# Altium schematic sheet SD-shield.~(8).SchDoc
size A; SheetNumber: 1; SheetTotal: 1
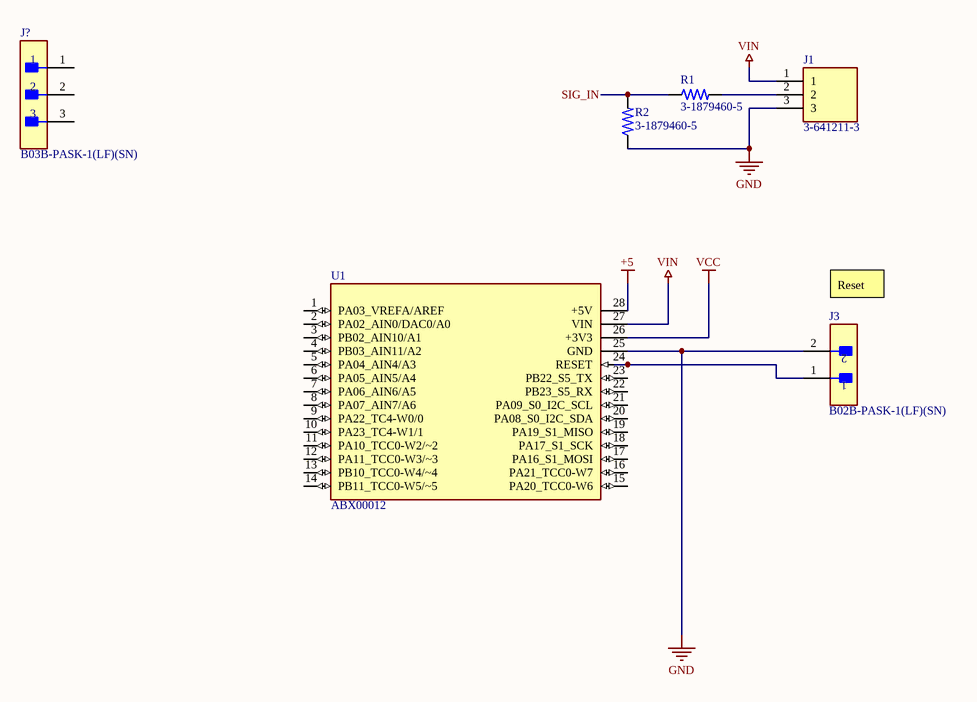
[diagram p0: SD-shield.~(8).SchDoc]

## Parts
J1  3-641211-3  [TE_3-641211-3]
J3  B02B-PASK-1(LF)(SN)  [FP-B02B-PASK-1_LF_SN-MFG]
J?  B03B-PASK-1(LF)(SN)  [FP-B03B-PASK-1_LF_SN-MFG]
R1  3-1879460-5  [RESC1608X50N]
R2  3-1879460-5  [RESC1608X50N]
U1  ABX00012  [ARDUINO_ABX00012]

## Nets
+5: U1.28(+5V)
GND: J1.3 J3.2 R2.1 U1.25(GND)
VCC: U1.26(+3V3)
VIN: J1.1 U1.27(VIN)
SIG_IN: R1.1 R2.2
NetJ1_2: J1.2 R1.2
NetJ3_1: J3.1 U1.24(RESET)

Not connected (* = marked no-connect by the designer): J? 1 2 3; U1 1(PA03_VREFA/AREF) 2(PA02_AIN0/DAC0/A0) 3(PB02_AIN10/A1) 4(PB03_AIN11/A2) 5(PA04_AIN4/A3) 6(PA05_AIN5/A4) 7(PA06_AIN6/A5) 8(PA07_AIN7/A6) 9(PA22_TC4-W0/0) 10(PA23_TC4-W1/1) 11(PA10_TCC0-W2/~2) 12(PA11_TCC0-W3/~3) 13(PB10_TCC0-W4/~4) 14(PB11_TCC0-W5/~5) 15(PA20_TCC0-W6) 16(PA21_TCC0-W7) 17(PA16_S1_MOSI) 18(PA17_S1_SCK) 19(PA19_S1_MISO) 20(PA08_S0_I2C_SDA) 21(PA09_S0_I2C_SCL) 22(PB23_S5_RX) 23(PB22_S5_TX)

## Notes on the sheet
- Reset

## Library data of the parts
J3 = CMP-17439-000415-1: CONN HEADER VERT 2POS 2MM; Number of Contacts: 2; Current Rating: 3A; Insulation Resistance: 1GR; Mated Stacking Heights: 14.9mm; Voltage Rating: 250V; Gender: Male
J? = CMP-17439-000193-1: CONN HEADER VERT 3POS 2MM; Voltage Rating: 250V; Current Rating: 3A; Mated Stacking Heights: 14.9mm; Number of Positions: 3
R1 R2 = 3-1879460-5: RES 0.27 OHM 1% 1/10W 0603; Resistance: 27; MF: TE Connectivity; Power_Rating: .1 W
U1 = ABX00012: MKR footprint/pins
